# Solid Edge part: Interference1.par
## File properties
Last saved by: Cadcim
Revision: 44
Accuracy: 0.99
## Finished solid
Body 1: solid body, 6 faces, 6 edges, 0 vertices.
  Faces by surface: cylinder 3, cone 2, plane 1
  Edges by curve: circle 4, intersection 2
Body 2: solid body, 6 faces, 6 edges, 0 vertices.
  Faces by surface: cylinder 3, cone 2, plane 1
  Edges by curve: circle 4, intersection 2
Body 3: solid body, 6 faces, 6 edges, 0 vertices.
  Faces by surface: cylinder 3, cone 2, plane 1
  Edges by curve: circle 4, intersection 2
Body 4: solid body, 6 faces, 6 edges, 0 vertices.
  Faces by surface: cylinder 3, cone 2, plane 1
  Edges by curve: circle 4, intersection 2
Bounding box of the edges (mm): 152.400 x 152.400 x 25.400, from (-76.2, -76.2, 70.5218) to (76.2, 76.2, 95.9218).
Cylindrical faces by radius (mm): R9.5123 x4, R12.7 x4, R76.2 x4
Conical faces (half-angle, radius in mm at the cone's reference point): 45 deg R12.7 x4, 59 deg R9.5123 x4
Planar faces by outward normal: +x 1, +y 1, -x 1, -y 1
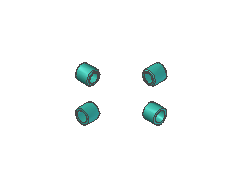
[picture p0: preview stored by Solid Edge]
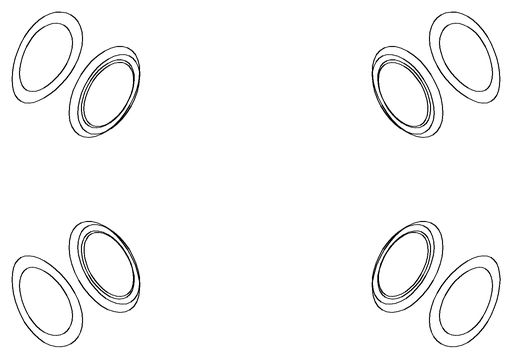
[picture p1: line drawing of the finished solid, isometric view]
